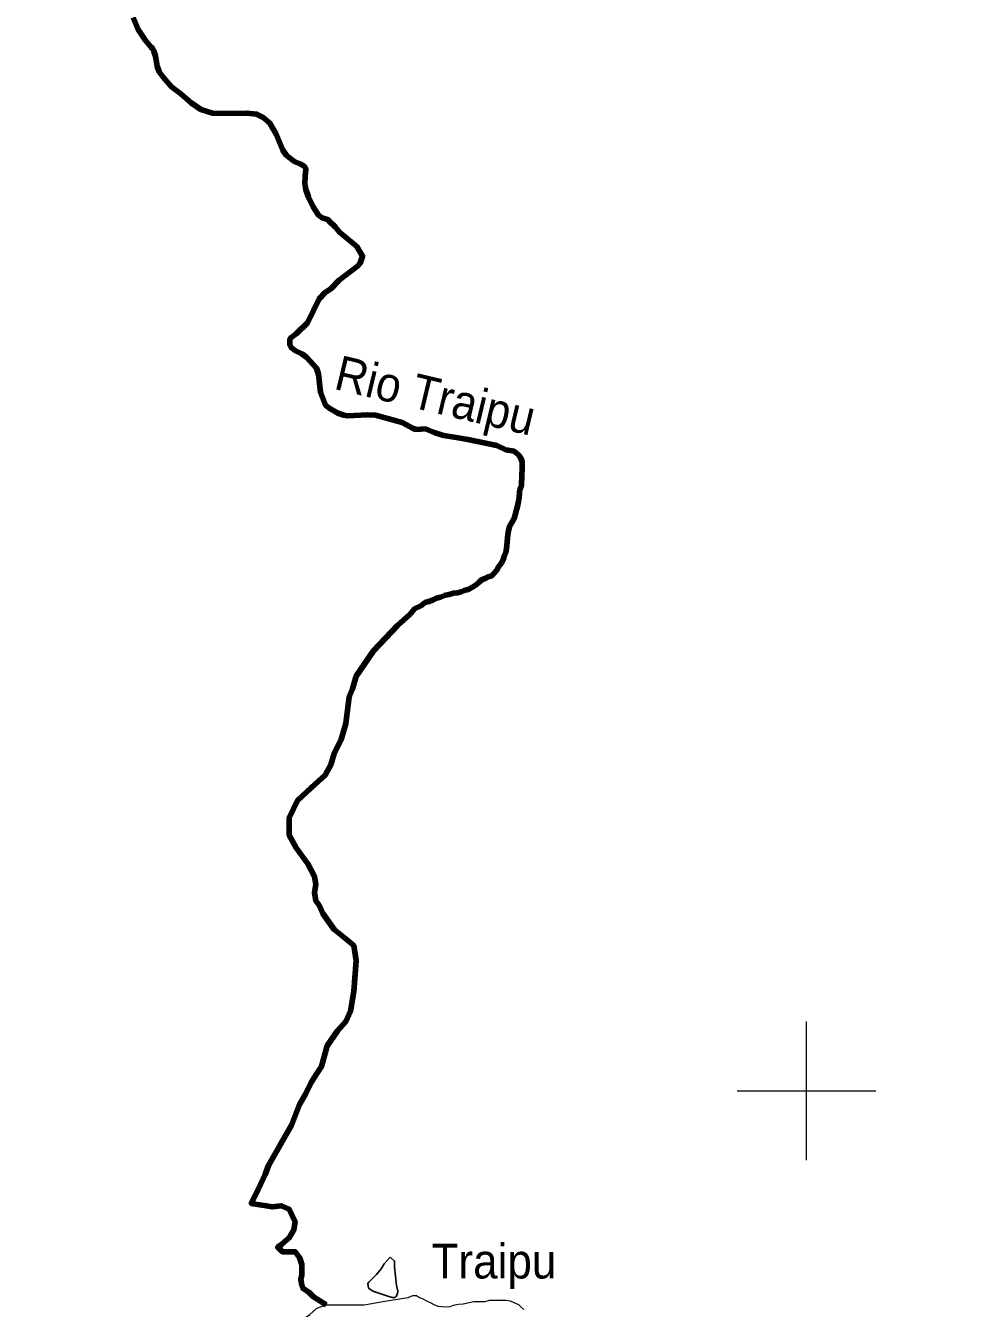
# Model space of a CAD drawing. Extents: x -1643653 to 4543381, y 1624270 to 13878484.
# Drawn here: x 713736 to 727176, y 8896862 to 8915367 of the extents above; entities that cross this region are included whole.
import ezdxf
from ezdxf.enums import TextEntityAlignment as Align

# ---------------------------------------------------------------- set-up
doc = ezdxf.new("R2010")
doc.units = 0
doc.header["$LTSCALE"] = 160
for name, color, linetype, lineweight in [('2', 7, 'Continuous', 13), ('21', 7, 'Continuous', 25), ('24', 7, 'Continuous', 25), ('25', 7, 'Continuous', 13), ('53', 7, 'Continuous', 106), ('60', 7, 'Continuous', 13)]:
    doc.layers.add(name, color=color, linetype=linetype, lineweight=lineweight)
doc.layers.add('41', color=7, linetype='Continuous')
doc.layers.add('49', color=7, linetype='Continuous')

msp = doc.modelspace()

# ---------------------------------------------------------------- linework, layer by layer
at = {"layer": '2'}
for p, q in [((725000, 8899000), (725000, 8901000)), ((724000, 8900000), (726000, 8900000))]:
    msp.add_line(p, q, dxfattribs=at)
at = {"layer": '21'}
msp.add_lwpolyline([(718993.1, 8897599.9), (719057.4, 8897544.6), (719055.9, 8897461.4), (719085.3, 8897192.5), (719103.1, 8897108.8), (719098.1, 8897076.1), (719079.4, 8897033), (719065.5, 8897020), (719028.2, 8897020.1), (718974.7, 8897034.1), (718746.2, 8897111.7), (718679.7, 8897153.1), (718671.6, 8897221.2), (718685, 8897240.1), (718799.2, 8897348.2), (718862.4, 8897430.9), (718906.6, 8897502.9)], close=True, dxfattribs=at)
at = {"layer": '24', "lineweight": 53}
for points in [[(715285.6, 8915483), (715360.4, 8915309.1), (715466.5, 8915151.7), (715544.8, 8915057.8), (715568.8, 8915033.9), (715582.8, 8914999.5)], [(715582.8, 8914999.5), (715607.3, 8914926.5), (715630.8, 8914782.1), (715664.2, 8914698.4), (715720.4, 8914621.3), (715841.4, 8914484.8), (715976.3, 8914382.9), (716121.9, 8914251.7), (716262.7, 8914158.2), (716430.6, 8914102.4), (716723.3, 8914098.2), (716931, 8914106.3), (717067.3, 8914089.8), (717160, 8914040), (717258.6, 8913960.8), (717350.2, 8913798.9), (717444.9, 8913569.6), (717500.7, 8913495.3), (717620.4, 8913403.7), (717696.9, 8913374.6), (717753.4, 8913338.3), (717771.3, 8913315.3), (717779.7, 8913284.7), (717767.4, 8913198.7), (717765.2, 8913088.6), (717776, 8913003.3), (717816.4, 8912891.5), (717881.6, 8912752), (717959.7, 8912633.8), (718012.2, 8912595.1), (718103.9, 8912566), (718108.4, 8912552.9), (718200.6, 8912462.7), (718263.8, 8912388), (718510.9, 8912180.7), (718595.9, 8912042.5), (718559.6, 8911942), (718525.1, 8911895.3), (718256.7, 8911695.7), (718139.8, 8911569.1), (718058.8, 8911518.2), (717971, 8911425.9), (717799.8, 8911079.5), (717637.2, 8910919.9), (717559.9, 8910863.9), (717548.7, 8910844.9), (717546.6, 8910765.8), (717564.2, 8910723.9), (717629.5, 8910673.2), (717717.9, 8910632.5), (717786.1, 8910583.9), (717932.5, 8910426.1), (717961.9, 8910338.5), (717987.1, 8910076.6), (718063.3, 8909892.7), (718110.2, 8909851.7), (718240.9, 8909774.5), (718323.8, 8909744.9), (718380.9, 8909735.3), (718665.9, 8909753.1), (718783.6, 8909747.4), (719169.5, 8909639.4), (719326.4, 8909556.3)], [(719326.4, 8909556.3), (719371.3, 8909542.5), (719371.3, 8909542.5), (719504.5, 8909548.1), (719504.5, 8909548.1), (719504.5, 8909548.1), (719626.5, 8909498.2)], [(719626.5, 8909498.2), (719765.2, 8909453.8), (719765.2, 8909453.8), (719765.2, 8909453.8), (719765.2, 8909453.8), (719948.4, 8909426.1), (719948.4, 8909426.1), (719948.4, 8909426.1), (720114.8, 8909398.4), (720114.8, 8909398.4), (720114.8, 8909398.4), (720392.3, 8909337.4), (720392.3, 8909337.4), (720392.3, 8909337.4), (720392.3, 8909337.4), (720531, 8909309.6), (720531, 8909309.6), (720531, 8909309.6), (720664.2, 8909248.6), (720780.7, 8909226.5), (720848.9, 8909167.8), (720879.1, 8909126.9), (720899.1, 8909075.8), (720898.7, 8909024.9), (720898.3, 8908963.8), (720892.8, 8908897.6), (720892.3, 8908831.3), (720886.9, 8908780.4), (720886.5, 8908724.4), (720865.8, 8908678.7), (720860.4, 8908622.7), (720854.9, 8908561.6), (720844.3, 8908500.6), (720828.6, 8908434.4), (720818, 8908383.6), (720797.2, 8908307.3), (720781.6, 8908256.4), (720750.7, 8908200.6), (720714.6, 8908139.7), (720699, 8908078.7), (720693.5, 8908027.8), (720680.1, 8907917.9)], [(720680.1, 8907917.9), (720671.8, 8907819.1), (720661.2, 8907768.2), (720640.5, 8907712.3), (720624.9, 8907661.5), (720594, 8907605.6), (720558.1, 8907560), (720532.3, 8907509.3), (720496.4, 8907468.7), (720460.5, 8907428.2), (720409.6, 8907413.3), (720363.7, 8907393.2), (720312.7, 8907373.1), (720276.8, 8907337.7), (720241, 8907302.3), (720179.7, 8907267), (720118.4, 8907231.8), (720062.3, 8907216.8), (720016.4, 8907196.8), (719965.5, 8907181.8), (719909.5, 8907177.1), (719843.3, 8907162.2), (719792.3, 8907152.3), (719720.9, 8907122.2), (719664.9, 8907107.3), (719603.6, 8907077.1), (719552.6, 8907057.1), (719496.6, 8907042.2), (719445.4, 8907001.8), (719343.4, 8906951.5), (719283.6, 8906877)], [(719283.6, 8906877), (719100.8, 8906711), (718751.9, 8906345.6), (718502.7, 8905980.3), (718452.8, 8905797.7), (718403, 8905681.4), (718353.1, 8905299.5), (718286.7, 8905067), (718187, 8904867.8), (718137.2, 8904701.7), (718054.1, 8904552.2), (717859.9, 8904374.3), (717854.7, 8904369.6)], [(717854.7, 8904369.6), (717655.3, 8904186.9), (717539, 8903937.8), (717539, 8903688.8), (717638.7, 8903506.1), (717804.9, 8903273.6), (717904.6, 8903091), (717921.2, 8902974.7), (717904.6, 8902858.5), (717921.2, 8902742.3), (717971.1, 8902675.9), (718020.9, 8902559.6), (718187, 8902327.1), (718353.2, 8902194.3), (718469.5, 8902094.7), (718502.7, 8901878.8), (718469.5, 8901430.4), (718419.6, 8901148.2), (718353.2, 8900998.7), (718236.8, 8900865.9), (718087.3, 8900650), (718004.2, 8900351.1), (717937.8, 8900251.5), (717854.7, 8900118.6), (717771.7, 8899952.6), (717688.6, 8899803.1), (717572.3, 8899504.2), (717240, 8898923), (717190.1, 8898790.2), (717090.4, 8898574.3), (716990.8, 8898375.1), (717206.8, 8898341.9), (717289.8, 8898325.2), (717422.7, 8898341.9), (717539, 8898292), (717622.1, 8898109.4), (717605.5, 8897993.1), (717539, 8897876.9), (717472.6, 8897827.1), (717422.7, 8897777.3), (717372.9, 8897744.1), (717439.4, 8897677.6), (717622.1, 8897677.6), (717688.6, 8897594.6), (717721.8, 8897495), (717721.8, 8897395.3), (717721.8, 8897345.5), (717705.2, 8897279.1), (717721.8, 8897196.1), (717738.4, 8897146.3), (717821.5, 8897096.4), (717888, 8897030), (718070.7, 8896913.8)]]:
    msp.add_lwpolyline(points, dxfattribs=at)
at = {"layer": '25'}
for points in [[(716671.9, 8896141.4), (716736, 8896160), (716876.8, 8896172.9), (716996.8, 8896216.3), (717443.2, 8896481.3), (717658.9, 8896651.8), (717833.2, 8896772.8), (717934, 8896865.6), (718070.7, 8896913.8), (718220.3, 8896913.8), (718619, 8896913.8), (718918.1, 8896963.6), (719252.2, 8897020.3)], [(719252.2, 8897020.3), (719320.1, 8897049.2), (719376, 8897048.8), (719416.5, 8897018), (719467.2, 8896997.3), (719517.9, 8896971.5), (719578.7, 8896940.5), (719624.3, 8896914.8), (719680.1, 8896894), (719736.1, 8896888.6), (719797.1, 8896883.1), (719858.1, 8896887.8), (719909.1, 8896907.8), (719980.4, 8896922.7), (720046.6, 8896927.3), (720199.4, 8896962), (720255.3, 8896961.7), (720306.2, 8896961.3), (720362.2, 8896961), (720428.4, 8896980.9), (720479.3, 8896980.6), (720540.3, 8896980.2), (720606.4, 8896979.8), (720667.5, 8896979.4), (720723.3, 8896968.8), (720779.1, 8896948.1), (720845, 8896917.1), (720880.4, 8896881.2), (720920.8, 8896845.3)]]:
    msp.add_lwpolyline(points, dxfattribs=at)
at = {"layer": '53'}
for points in [[(715285.6, 8915483), (715360.4, 8915309.1), (715466.5, 8915151.7), (715544.8, 8915057.8), (715568.8, 8915033.9), (715582.8, 8914999.5)], [(715285.6, 8915483), (715360.4, 8915309.1), (715466.5, 8915151.7), (715544.8, 8915057.8), (715568.8, 8915033.9), (715582.8, 8914999.5)], [(715285.6, 8915483), (715360.4, 8915309.1), (715466.5, 8915151.7), (715544.8, 8915057.8), (715568.8, 8915033.9), (715582.8, 8914999.5)], [(715582.8, 8914999.5), (715607.3, 8914926.5), (715630.8, 8914782.1), (715664.2, 8914698.4), (715720.4, 8914621.3), (715841.4, 8914484.8), (715976.3, 8914382.9), (716121.9, 8914251.7), (716262.7, 8914158.2), (716430.6, 8914102.4), (716723.3, 8914098.2), (716931, 8914106.3), (717067.3, 8914089.8), (717160, 8914040), (717258.6, 8913960.8), (717350.2, 8913798.9), (717444.9, 8913569.6), (717500.7, 8913495.3), (717620.4, 8913403.7), (717696.9, 8913374.6), (717753.4, 8913338.3), (717771.3, 8913315.3), (717779.7, 8913284.7), (717767.4, 8913198.7), (717765.2, 8913088.6), (717776, 8913003.3), (717816.4, 8912891.5), (717881.6, 8912752), (717959.7, 8912633.8), (718012.2, 8912595.1), (718103.9, 8912566), (718108.4, 8912552.9), (718200.6, 8912462.7), (718263.8, 8912388), (718510.9, 8912180.7), (718595.9, 8912042.5), (718559.6, 8911942), (718525.1, 8911895.3), (718256.7, 8911695.7), (718139.8, 8911569.1), (718058.8, 8911518.2), (717971, 8911425.9), (717799.8, 8911079.5), (717637.2, 8910919.9), (717559.9, 8910863.9), (717548.7, 8910844.9), (717546.6, 8910765.8), (717564.2, 8910723.9), (717629.5, 8910673.2), (717717.9, 8910632.5), (717786.1, 8910583.9), (717932.5, 8910426.1), (717961.9, 8910338.5), (717987.1, 8910076.6), (718063.3, 8909892.7), (718110.2, 8909851.7), (718240.9, 8909774.5), (718323.8, 8909744.9), (718380.9, 8909735.3), (718665.9, 8909753.1), (718783.6, 8909747.4), (719169.5, 8909639.4), (719326.4, 8909556.3)], [(715582.8, 8914999.5), (715607.3, 8914926.5), (715630.8, 8914782.1), (715664.2, 8914698.4), (715720.4, 8914621.3), (715841.4, 8914484.8), (715976.3, 8914382.9), (716121.9, 8914251.7), (716262.7, 8914158.2), (716430.6, 8914102.4), (716723.3, 8914098.2), (716931, 8914106.3), (717067.3, 8914089.8), (717160, 8914040), (717258.6, 8913960.8), (717350.2, 8913798.9), (717444.9, 8913569.6), (717500.7, 8913495.3), (717620.4, 8913403.7), (717696.9, 8913374.6), (717753.4, 8913338.3), (717771.3, 8913315.3), (717779.7, 8913284.7), (717767.4, 8913198.7), (717765.2, 8913088.6), (717776, 8913003.3), (717816.4, 8912891.5), (717881.6, 8912752), (717959.7, 8912633.8), (718012.2, 8912595.1), (718103.9, 8912566), (718108.4, 8912552.9), (718200.6, 8912462.7), (718263.8, 8912388), (718510.9, 8912180.7), (718595.9, 8912042.5), (718559.6, 8911942), (718525.1, 8911895.3), (718256.7, 8911695.7), (718139.8, 8911569.1), (718058.8, 8911518.2), (717971, 8911425.9), (717799.8, 8911079.5), (717637.2, 8910919.9), (717559.9, 8910863.9), (717548.7, 8910844.9), (717546.6, 8910765.8), (717564.2, 8910723.9), (717629.5, 8910673.2), (717717.9, 8910632.5), (717786.1, 8910583.9), (717932.5, 8910426.1), (717961.9, 8910338.5), (717987.1, 8910076.6), (718063.3, 8909892.7), (718110.2, 8909851.7), (718240.9, 8909774.5), (718323.8, 8909744.9), (718380.9, 8909735.3), (718665.9, 8909753.1), (718783.6, 8909747.4), (719169.5, 8909639.4), (719326.4, 8909556.3)], [(715582.8, 8914999.5), (715607.3, 8914926.5), (715630.8, 8914782.1), (715664.2, 8914698.4), (715720.4, 8914621.3), (715841.4, 8914484.8), (715976.3, 8914382.9), (716121.9, 8914251.7), (716262.7, 8914158.2), (716430.6, 8914102.4), (716723.3, 8914098.2), (716931, 8914106.3), (717067.3, 8914089.8), (717160, 8914040), (717258.6, 8913960.8), (717350.2, 8913798.9), (717444.9, 8913569.6), (717500.7, 8913495.3), (717620.4, 8913403.7), (717696.9, 8913374.6), (717753.4, 8913338.3), (717771.3, 8913315.3), (717779.7, 8913284.7), (717767.4, 8913198.7), (717765.2, 8913088.6), (717776, 8913003.3), (717816.4, 8912891.5), (717881.6, 8912752), (717959.7, 8912633.8), (718012.2, 8912595.1), (718103.9, 8912566), (718108.4, 8912552.9), (718200.6, 8912462.7), (718263.8, 8912388), (718510.9, 8912180.7), (718595.9, 8912042.5), (718559.6, 8911942), (718525.1, 8911895.3), (718256.7, 8911695.7), (718139.8, 8911569.1), (718058.8, 8911518.2), (717971, 8911425.9), (717799.8, 8911079.5), (717637.2, 8910919.9), (717559.9, 8910863.9), (717548.7, 8910844.9), (717546.6, 8910765.8), (717564.2, 8910723.9), (717629.5, 8910673.2), (717717.9, 8910632.5), (717786.1, 8910583.9), (717932.5, 8910426.1), (717961.9, 8910338.5), (717987.1, 8910076.6), (718063.3, 8909892.7), (718110.2, 8909851.7), (718240.9, 8909774.5), (718323.8, 8909744.9), (718380.9, 8909735.3), (718665.9, 8909753.1), (718783.6, 8909747.4), (719169.5, 8909639.4), (719326.4, 8909556.3)], [(719326.4, 8909556.3), (719371.3, 8909542.5), (719371.3, 8909542.5), (719504.5, 8909548.1), (719504.5, 8909548.1), (719504.5, 8909548.1), (719626.5, 8909498.2)], [(719326.4, 8909556.3), (719371.3, 8909542.5), (719371.3, 8909542.5), (719504.5, 8909548.1), (719504.5, 8909548.1), (719504.5, 8909548.1), (719626.5, 8909498.2)], [(719326.4, 8909556.3), (719371.3, 8909542.5), (719371.3, 8909542.5), (719504.5, 8909548.1), (719504.5, 8909548.1), (719504.5, 8909548.1), (719626.5, 8909498.2)], [(719626.5, 8909498.2), (719765.2, 8909453.8), (719765.2, 8909453.8), (719765.2, 8909453.8), (719765.2, 8909453.8), (719948.4, 8909426.1), (719948.4, 8909426.1), (719948.4, 8909426.1), (720114.8, 8909398.4), (720114.8, 8909398.4), (720114.8, 8909398.4), (720392.3, 8909337.4), (720392.3, 8909337.4), (720392.3, 8909337.4), (720392.3, 8909337.4), (720531, 8909309.6), (720531, 8909309.6), (720531, 8909309.6), (720664.2, 8909248.6), (720780.7, 8909226.5), (720848.9, 8909167.8), (720879.1, 8909126.9), (720899.1, 8909075.8), (720898.7, 8909024.9), (720898.3, 8908963.8), (720892.8, 8908897.6), (720892.3, 8908831.3), (720886.9, 8908780.4), (720886.5, 8908724.4), (720865.8, 8908678.7), (720860.4, 8908622.7), (720854.9, 8908561.6), (720844.3, 8908500.6), (720828.6, 8908434.4), (720818, 8908383.6), (720797.2, 8908307.3), (720781.6, 8908256.4), (720750.7, 8908200.6), (720714.6, 8908139.7), (720699, 8908078.7), (720693.5, 8908027.8), (720680.1, 8907917.9)], [(719626.5, 8909498.2), (719765.2, 8909453.8), (719765.2, 8909453.8), (719765.2, 8909453.8), (719765.2, 8909453.8), (719948.4, 8909426.1), (719948.4, 8909426.1), (719948.4, 8909426.1), (720114.8, 8909398.4), (720114.8, 8909398.4), (720114.8, 8909398.4), (720392.3, 8909337.4), (720392.3, 8909337.4), (720392.3, 8909337.4), (720392.3, 8909337.4), (720531, 8909309.6), (720531, 8909309.6), (720531, 8909309.6), (720664.2, 8909248.6), (720780.7, 8909226.5), (720848.9, 8909167.8), (720879.1, 8909126.9), (720899.1, 8909075.8), (720898.7, 8909024.9), (720898.3, 8908963.8), (720892.8, 8908897.6), (720892.3, 8908831.3), (720886.9, 8908780.4), (720886.5, 8908724.4), (720865.8, 8908678.7), (720860.4, 8908622.7), (720854.9, 8908561.6), (720844.3, 8908500.6), (720828.6, 8908434.4), (720818, 8908383.6), (720797.2, 8908307.3), (720781.6, 8908256.4), (720750.7, 8908200.6), (720714.6, 8908139.7), (720699, 8908078.7), (720693.5, 8908027.8), (720680.1, 8907917.9)], [(719626.5, 8909498.2), (719765.2, 8909453.8), (719765.2, 8909453.8), (719765.2, 8909453.8), (719765.2, 8909453.8), (719948.4, 8909426.1), (719948.4, 8909426.1), (719948.4, 8909426.1), (720114.8, 8909398.4), (720114.8, 8909398.4), (720114.8, 8909398.4), (720392.3, 8909337.4), (720392.3, 8909337.4), (720392.3, 8909337.4), (720392.3, 8909337.4), (720531, 8909309.6), (720531, 8909309.6), (720531, 8909309.6), (720664.2, 8909248.6), (720780.7, 8909226.5), (720848.9, 8909167.8), (720879.1, 8909126.9), (720899.1, 8909075.8), (720898.7, 8909024.9), (720898.3, 8908963.8), (720892.8, 8908897.6), (720892.3, 8908831.3), (720886.9, 8908780.4), (720886.5, 8908724.4), (720865.8, 8908678.7), (720860.4, 8908622.7), (720854.9, 8908561.6), (720844.3, 8908500.6), (720828.6, 8908434.4), (720818, 8908383.6), (720797.2, 8908307.3), (720781.6, 8908256.4), (720750.7, 8908200.6), (720714.6, 8908139.7), (720699, 8908078.7), (720693.5, 8908027.8), (720680.1, 8907917.9)], [(720680.1, 8907917.9), (720671.8, 8907819.1), (720661.2, 8907768.2), (720640.5, 8907712.3), (720624.9, 8907661.5), (720594, 8907605.6), (720558.1, 8907560), (720532.3, 8907509.3), (720496.4, 8907468.7), (720460.5, 8907428.2), (720409.6, 8907413.3), (720363.7, 8907393.2), (720312.7, 8907373.1), (720276.8, 8907337.7), (720241, 8907302.3), (720179.7, 8907267), (720118.4, 8907231.8), (720062.3, 8907216.8), (720016.4, 8907196.8), (719965.5, 8907181.8), (719909.5, 8907177.1), (719843.3, 8907162.2), (719792.3, 8907152.3), (719720.9, 8907122.2), (719664.9, 8907107.3), (719603.6, 8907077.1), (719552.6, 8907057.1), (719496.6, 8907042.2), (719445.4, 8907001.8), (719343.4, 8906951.5), (719283.6, 8906877)], [(720680.1, 8907917.9), (720671.8, 8907819.1), (720661.2, 8907768.2), (720640.5, 8907712.3), (720624.9, 8907661.5), (720594, 8907605.6), (720558.1, 8907560), (720532.3, 8907509.3), (720496.4, 8907468.7), (720460.5, 8907428.2), (720409.6, 8907413.3), (720363.7, 8907393.2), (720312.7, 8907373.1), (720276.8, 8907337.7), (720241, 8907302.3), (720179.7, 8907267), (720118.4, 8907231.8), (720062.3, 8907216.8), (720016.4, 8907196.8), (719965.5, 8907181.8), (719909.5, 8907177.1), (719843.3, 8907162.2), (719792.3, 8907152.3), (719720.9, 8907122.2), (719664.9, 8907107.3), (719603.6, 8907077.1), (719552.6, 8907057.1), (719496.6, 8907042.2), (719445.4, 8907001.8), (719343.4, 8906951.5), (719283.6, 8906877)], [(720680.1, 8907917.9), (720671.8, 8907819.1), (720661.2, 8907768.2), (720640.5, 8907712.3), (720624.9, 8907661.5), (720594, 8907605.6), (720558.1, 8907560), (720532.3, 8907509.3), (720496.4, 8907468.7), (720460.5, 8907428.2), (720409.6, 8907413.3), (720363.7, 8907393.2), (720312.7, 8907373.1), (720276.8, 8907337.7), (720241, 8907302.3), (720179.7, 8907267), (720118.4, 8907231.8), (720062.3, 8907216.8), (720016.4, 8907196.8), (719965.5, 8907181.8), (719909.5, 8907177.1), (719843.3, 8907162.2), (719792.3, 8907152.3), (719720.9, 8907122.2), (719664.9, 8907107.3), (719603.6, 8907077.1), (719552.6, 8907057.1), (719496.6, 8907042.2), (719445.4, 8907001.8), (719343.4, 8906951.5), (719283.6, 8906877)], [(719283.6, 8906877), (719100.8, 8906711), (718751.9, 8906345.6), (718502.7, 8905980.3), (718452.8, 8905797.7), (718403, 8905681.4), (718353.1, 8905299.5), (718286.7, 8905067), (718187, 8904867.8), (718137.2, 8904701.7), (718054.1, 8904552.2), (717859.9, 8904374.3), (717854.7, 8904369.6)], [(719283.6, 8906877), (719100.8, 8906711), (718751.9, 8906345.6), (718502.7, 8905980.3), (718452.8, 8905797.7), (718403, 8905681.4), (718353.1, 8905299.5), (718286.7, 8905067), (718187, 8904867.8), (718137.2, 8904701.7), (718054.1, 8904552.2), (717859.9, 8904374.3), (717854.7, 8904369.6)], [(719283.6, 8906877), (719100.8, 8906711), (718751.9, 8906345.6), (718502.7, 8905980.3), (718452.8, 8905797.7), (718403, 8905681.4), (718353.1, 8905299.5), (718286.7, 8905067), (718187, 8904867.8), (718137.2, 8904701.7), (718054.1, 8904552.2), (717859.9, 8904374.3), (717854.7, 8904369.6)], [(717854.7, 8904369.6), (717655.3, 8904186.9), (717539, 8903937.8), (717539, 8903688.8), (717638.7, 8903506.1), (717804.9, 8903273.6), (717904.6, 8903091), (717921.2, 8902974.7), (717904.6, 8902858.5), (717921.2, 8902742.3), (717971.1, 8902675.9), (718020.9, 8902559.6), (718187, 8902327.1), (718353.2, 8902194.3), (718469.5, 8902094.7), (718502.7, 8901878.8), (718469.5, 8901430.4), (718419.6, 8901148.2), (718353.2, 8900998.7), (718236.8, 8900865.9), (718087.3, 8900650), (718004.2, 8900351.1), (717937.8, 8900251.5), (717854.7, 8900118.6), (717771.7, 8899952.6), (717688.6, 8899803.1), (717572.3, 8899504.2), (717240, 8898923), (717190.1, 8898790.2), (717090.4, 8898574.3), (716990.8, 8898375.1), (717206.8, 8898341.9), (717289.8, 8898325.2), (717422.7, 8898341.9), (717539, 8898292), (717622.1, 8898109.4), (717605.5, 8897993.1), (717539, 8897876.9), (717472.6, 8897827.1), (717422.7, 8897777.3), (717372.9, 8897744.1), (717439.4, 8897677.6), (717622.1, 8897677.6), (717688.6, 8897594.6), (717721.8, 8897495), (717721.8, 8897395.3), (717721.8, 8897345.5), (717705.2, 8897279.1), (717721.8, 8897196.1), (717738.4, 8897146.3), (717821.5, 8897096.4), (717888, 8897030), (718070.7, 8896913.8)], [(717854.7, 8904369.6), (717655.3, 8904186.9), (717539, 8903937.8), (717539, 8903688.8), (717638.7, 8903506.1), (717804.9, 8903273.6), (717904.6, 8903091), (717921.2, 8902974.7), (717904.6, 8902858.5), (717921.2, 8902742.3), (717971.1, 8902675.9), (718020.9, 8902559.6), (718187, 8902327.1), (718353.2, 8902194.3), (718469.5, 8902094.7), (718502.7, 8901878.8), (718469.5, 8901430.4), (718419.6, 8901148.2), (718353.2, 8900998.7), (718236.8, 8900865.9), (718087.3, 8900650), (718004.2, 8900351.1), (717937.8, 8900251.5), (717854.7, 8900118.6), (717771.7, 8899952.6), (717688.6, 8899803.1), (717572.3, 8899504.2), (717240, 8898923), (717190.1, 8898790.2), (717090.4, 8898574.3), (716990.8, 8898375.1), (717206.8, 8898341.9), (717289.8, 8898325.2), (717422.7, 8898341.9), (717539, 8898292), (717622.1, 8898109.4), (717605.5, 8897993.1), (717539, 8897876.9), (717472.6, 8897827.1), (717422.7, 8897777.3), (717372.9, 8897744.1), (717439.4, 8897677.6), (717622.1, 8897677.6), (717688.6, 8897594.6), (717721.8, 8897495), (717721.8, 8897395.3), (717721.8, 8897345.5), (717705.2, 8897279.1), (717721.8, 8897196.1), (717738.4, 8897146.3), (717821.5, 8897096.4), (717888, 8897030), (718070.7, 8896913.8)], [(717854.7, 8904369.6), (717655.3, 8904186.9), (717539, 8903937.8), (717539, 8903688.8), (717638.7, 8903506.1), (717804.9, 8903273.6), (717904.6, 8903091), (717921.2, 8902974.7), (717904.6, 8902858.5), (717921.2, 8902742.3), (717971.1, 8902675.9), (718020.9, 8902559.6), (718187, 8902327.1), (718353.2, 8902194.3), (718469.5, 8902094.7), (718502.7, 8901878.8), (718469.5, 8901430.4), (718419.6, 8901148.2), (718353.2, 8900998.7), (718236.8, 8900865.9), (718087.3, 8900650), (718004.2, 8900351.1), (717937.8, 8900251.5), (717854.7, 8900118.6), (717771.7, 8899952.6), (717688.6, 8899803.1), (717572.3, 8899504.2), (717240, 8898923), (717190.1, 8898790.2), (717090.4, 8898574.3), (716990.8, 8898375.1), (717206.8, 8898341.9), (717289.8, 8898325.2), (717422.7, 8898341.9), (717539, 8898292), (717622.1, 8898109.4), (717605.5, 8897993.1), (717539, 8897876.9), (717472.6, 8897827.1), (717422.7, 8897777.3), (717372.9, 8897744.1), (717439.4, 8897677.6), (717622.1, 8897677.6), (717688.6, 8897594.6), (717721.8, 8897495), (717721.8, 8897395.3), (717721.8, 8897345.5), (717705.2, 8897279.1), (717721.8, 8897196.1), (717738.4, 8897146.3), (717821.5, 8897096.4), (717888, 8897030), (718070.7, 8896913.8)]]:
    msp.add_lwpolyline(points, dxfattribs=at)
at = {"layer": '60', "lineweight": 25}
msp.add_spline([(814781, 9009175.5), (814787.2, 9009173.4), (814796.9, 9009173.4), (814799.4, 9009172.4), (814805.1, 9009174.5), (814805.6, 9009176.5), (814811.7, 9009179.5), (814811.7, 9009179.5), (814801.5, 9009181), (814790.7, 9009181.5), (814784.1, 9009183.1), (814777.4, 9009185.1), (814778.4, 9009175.5)], degree=3, dxfattribs=at)

# ---------------------------------------------------------------- texts
at = {"layer": '41', "width": 0.95}
msp.add_text('Traipu', height=500, dxfattribs=at).set_placement((719591.1, 8897292.6))
at = {"layer": '49', "width": 0.95}
msp.add_text('Rio Traipu', height=500, rotation=346.601, dxfattribs=at).set_placement((719591, 8909789.6), align=Align.CENTER)

doc.saveas('drawing.dxf')
